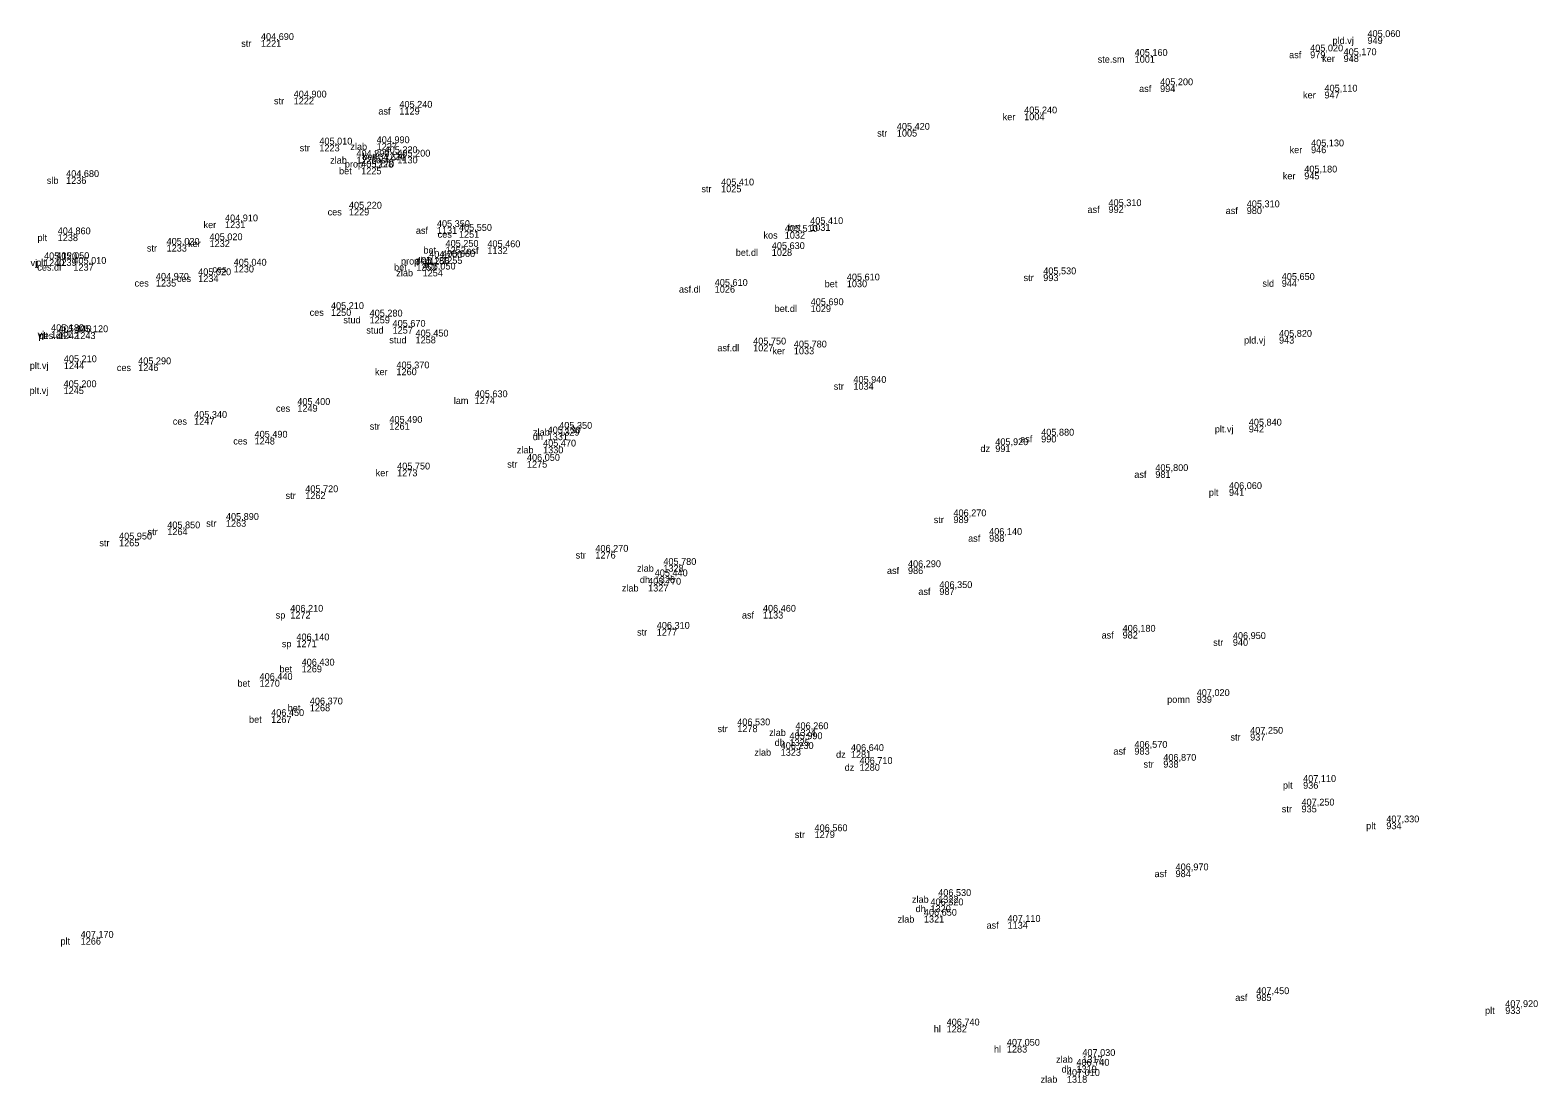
# Model space of a CAD drawing. Extents: x -747136 to -746138, y -1093274 to -1091717.
# Drawn here: x -747041.3 to -746975, y -1092218.2 to -1092171.8 of the extents above; entities that cross this region are included whole.
import ezdxf

# ---------------------------------------------------------------- set-up
doc = ezdxf.new("R2010")
doc.units = 0
for name, color, linetype in [('1029', 7, 'Continuous'), ('404', 7, 'Continuous'), ('424', 7, 'Continuous')]:
    doc.layers.add(name, color=color, linetype=linetype)

msp = doc.modelspace()

# ---------------------------------------------------------------- linework, layer by layer
at = {"layer": '404'}
for p, q in [((-747031.19, -1092172.27), (-747031.19, -1092172.27)), ((-746982.52, -1092172.14), (-746982.52, -1092172.14)), ((-746992.76, -1092172.97), (-746992.76, -1092172.97)), ((-746985.04, -1092172.77), (-746985.04, -1092172.77)), ((-746983.57, -1092172.94), (-746983.57, -1092172.94)), ((-746991.64, -1092174.26), (-746991.64, -1092174.26)), ((-747029.75, -1092174.8), (-747029.75, -1092174.8)), ((-746984.41, -1092174.54), (-746984.41, -1092174.54)), ((-747025.1, -1092175.25), (-747025.1, -1092175.25)), ((-746997.62, -1092175.5), (-746997.62, -1092175.5)), ((-747003.22, -1092176.22), (-747003.22, -1092176.22)), ((-747028.62, -1092176.87), (-747028.62, -1092176.87)), ((-747026.1, -1092176.81), (-747026.1, -1092176.81)), ((-746985, -1092176.95), (-746985, -1092176.95)), ((-747026.99, -1092177.41), (-747026.99, -1092177.41)), ((-747026.26, -1092177.58), (-747026.26, -1092177.58)), ((-747025.75, -1092177.25), (-747025.75, -1092177.25)), ((-747025.19, -1092177.4), (-747025.19, -1092177.4)), ((-747039.76, -1092178.3), (-747039.76, -1092178.3)), ((-747026.78, -1092177.88), (-747026.78, -1092177.88)), ((-746985.3, -1092178.1), (-746985.3, -1092178.1)), ((-747010.95, -1092178.67), (-747010.95, -1092178.67)), ((-747027.32, -1092179.69), (-747027.32, -1092179.69)), ((-746993.91, -1092179.58), (-746993.91, -1092179.58)), ((-746987.83, -1092179.63), (-746987.83, -1092179.63)), ((-747032.77, -1092180.25), (-747032.77, -1092180.25)), ((-747007.03, -1092180.37), (-747007.03, -1092180.37)), ((-747040.13, -1092180.82), (-747040.13, -1092180.82)), ((-747033.45, -1092181.08), (-747033.45, -1092181.08)), ((-747023.45, -1092180.5), (-747023.45, -1092180.5)), ((-747022.48, -1092180.67), (-747022.48, -1092180.67)), ((-747008.15, -1092180.71), (-747008.15, -1092180.71)), ((-747035.34, -1092181.28), (-747035.34, -1092181.28)), ((-747023.07, -1092181.37), (-747023.07, -1092181.37)), ((-747021.23, -1092181.39), (-747021.23, -1092181.39)), ((-747008.72, -1092181.47), (-747008.72, -1092181.47)), ((-747040.73, -1092181.92), (-747040.73, -1092181.92)), ((-747040.19, -1092181.91), (-747040.19, -1092181.91)), ((-747039.44, -1092182.12), (-747039.44, -1092182.12)), ((-747032.39, -1092182.2), (-747032.39, -1092182.2)), ((-747024.36, -1092182.12), (-747024.36, -1092182.12)), ((-747024.08, -1092182.37), (-747024.08, -1092182.37)), ((-747023.79, -1092181.85), (-747023.79, -1092181.85)), ((-747023.22, -1092181.82), (-747023.22, -1092181.82)), ((-747035.81, -1092182.82), (-747035.81, -1092182.82)), ((-747033.95, -1092182.62), (-747033.95, -1092182.62)), ((-747011.23, -1092183.09), (-747011.23, -1092183.09)), ((-747005.42, -1092182.85), (-747005.42, -1092182.85)), ((-746996.78, -1092182.58), (-746996.78, -1092182.58)), ((-746986.29, -1092182.83), (-746986.29, -1092182.83)), ((-747028.11, -1092184.11), (-747028.11, -1092184.11)), ((-747026.41, -1092184.44), (-747026.41, -1092184.44)), ((-747007.01, -1092183.94), (-747007.01, -1092183.94)), ((-747040.42, -1092185.08), (-747040.42, -1092185.08)), ((-747025.4, -1092184.89), (-747025.4, -1092184.89)), ((-747040.09, -1092185.13), (-747040.09, -1092185.13)), ((-747039.36, -1092185.13), (-747039.36, -1092185.13)), ((-747024.39, -1092185.32), (-747024.39, -1092185.32)), ((-747009.54, -1092185.67), (-747009.54, -1092185.67)), ((-746986.41, -1092185.33), (-746986.41, -1092185.33)), ((-747007.75, -1092185.8), (-747007.75, -1092185.8)), ((-747039.86, -1092186.45), (-747039.86, -1092186.45)), ((-747036.59, -1092186.54), (-747036.59, -1092186.54)), ((-747025.23, -1092186.72), (-747025.23, -1092186.72)), ((-747039.87, -1092187.55), (-747039.87, -1092187.55)), ((-747005.13, -1092187.36), (-747005.13, -1092187.36)), ((-747029.59, -1092188.33), (-747029.59, -1092188.33)), ((-747021.79, -1092187.99), (-747021.79, -1092187.99)), ((-747034.13, -1092188.9), (-747034.13, -1092188.9)), ((-747025.54, -1092189.12), (-747025.54, -1092189.12)), ((-747018.58, -1092189.58), (-747018.58, -1092189.58)), ((-747018.07, -1092189.38), (-747018.07, -1092189.38)), ((-746996.87, -1092189.68), (-746996.87, -1092189.68)), ((-746987.74, -1092189.24), (-746987.74, -1092189.24)), ((-747031.47, -1092189.77), (-747031.47, -1092189.77)), ((-747018.78, -1092190.16), (-747018.78, -1092190.16)), ((-746998.89, -1092190.1), (-746998.89, -1092190.1)), ((-747019.49, -1092190.79), (-747019.49, -1092190.79)), ((-747025.2, -1092191.17), (-747025.2, -1092191.17)), ((-746991.85, -1092191.24), (-746991.85, -1092191.24)), ((-747029.24, -1092192.17), (-747029.24, -1092192.17)), ((-746988.61, -1092192.03), (-746988.61, -1092192.03)), ((-747032.73, -1092193.39), (-747032.73, -1092193.39)), ((-747000.73, -1092193.23), (-747000.73, -1092193.23)), ((-747037.43, -1092194.25), (-747037.43, -1092194.25)), ((-747035.31, -1092193.76), (-747035.31, -1092193.76)), ((-746999.16, -1092194.05), (-746999.16, -1092194.05)), ((-747016.48, -1092194.79), (-747016.48, -1092194.79)), ((-747013.49, -1092195.37), (-747013.49, -1092195.37)), ((-747002.73, -1092195.47), (-747002.73, -1092195.47)), ((-747014.16, -1092196.24), (-747014.16, -1092196.24)), ((-747013.87, -1092195.87), (-747013.87, -1092195.87)), ((-747001.35, -1092196.39), (-747001.35, -1092196.39)), ((-747029.9, -1092197.43), (-747029.9, -1092197.43)), ((-747009.11, -1092197.43), (-747009.11, -1092197.43)), ((-747013.78, -1092198.18), (-747013.78, -1092198.18)), ((-746993.29, -1092198.31), (-746993.29, -1092198.31)), ((-747029.63, -1092198.69), (-747029.63, -1092198.69)), ((-746988.44, -1092198.63), (-746988.44, -1092198.63)), ((-747029.4, -1092199.8), (-747029.4, -1092199.8)), ((-747031.25, -1092200.43), (-747031.25, -1092200.43)), ((-747029.04, -1092201.51), (-747029.04, -1092201.51)), ((-746990.03, -1092201.14), (-746990.03, -1092201.14)), ((-747030.74, -1092202.02), (-747030.74, -1092202.02)), ((-747010.24, -1092202.43), (-747010.24, -1092202.43)), ((-747007.68, -1092202.6), (-747007.68, -1092202.6)), ((-746987.68, -1092202.8), (-746987.68, -1092202.8)), ((-747008.33, -1092203.47), (-747008.33, -1092203.47)), ((-747007.94, -1092203.04), (-747007.94, -1092203.04)), ((-747005.24, -1092203.56), (-747005.24, -1092203.56)), ((-746992.77, -1092203.42), (-746992.77, -1092203.42)), ((-747004.86, -1092204.13), (-747004.86, -1092204.13)), ((-746991.5, -1092203.99), (-746991.5, -1092203.99)), ((-746985.35, -1092204.92), (-746985.35, -1092204.92)), ((-746985.42, -1092205.96), (-746985.42, -1092205.96)), ((-746981.69, -1092206.7), (-746981.69, -1092206.7)), ((-747006.84, -1092207.09), (-747006.84, -1092207.09)), ((-746990.96, -1092208.81), (-746990.96, -1092208.81)), ((-747001.4, -1092209.94), (-747001.4, -1092209.94)), ((-747002.03, -1092210.81), (-747002.03, -1092210.81)), ((-747001.74, -1092210.35), (-747001.74, -1092210.35)), ((-746998.35, -1092211.08), (-746998.35, -1092211.08)), ((-747039.12, -1092211.78), (-747039.12, -1092211.78)), ((-746987.41, -1092214.26), (-746987.41, -1092214.26)), ((-746976.46, -1092214.83), (-746976.46, -1092214.83)), ((-747001.03, -1092215.64), (-747001.03, -1092215.64)), ((-746998.38, -1092216.53), (-746998.38, -1092216.53)), ((-746995.32, -1092217.41), (-746995.32, -1092217.41)), ((-746995.06, -1092216.98), (-746995.06, -1092216.98)), ((-746995.74, -1092217.86), (-746995.74, -1092217.86))]:
    msp.add_line(p, q, dxfattribs=at)

# ---------------------------------------------------------------- texts
at = {"layer": '1029'}
for s, p in [('405,060', (-746982.52, -1092172.14)), ('404,690', (-747031.19, -1092172.27)), ('405,020', (-746985.04, -1092172.77)), ('405,160', (-746992.76, -1092172.97)), ('405,170', (-746983.57, -1092172.94)), ('404,900', (-747029.75, -1092174.8)), ('405,200', (-746991.64, -1092174.26)), ('405,110', (-746984.41, -1092174.54)), ('405,240', (-747025.1, -1092175.25)), ('405,240', (-746997.62, -1092175.5)), ('405,420', (-747003.22, -1092176.22)), ('405,010', (-747028.62, -1092176.87)), ('404,890', (-747026.99, -1092177.41)), ('404,990', (-747026.1, -1092176.81)), ('405,220', (-747025.75, -1092177.25)), ('405,200', (-747025.19, -1092177.4)), ('405,130', (-746985, -1092176.95)), ('405,170', (-747026.78, -1092177.88)), ('404,670', (-747026.26, -1092177.58)), ('405,180', (-746985.3, -1092178.1)), ('404,680', (-747039.76, -1092178.3)), ('405,410', (-747010.95, -1092178.67)), ('405,220', (-747027.32, -1092179.69)), ('405,310', (-746993.91, -1092179.58)), ('405,310', (-746987.83, -1092179.63)), ('404,910', (-747032.77, -1092180.25)), ('405,350', (-747023.45, -1092180.5)), ('405,550', (-747022.48, -1092180.67)), ('405,510', (-747008.15, -1092180.71)), ('405,410', (-747007.03, -1092180.37)), ('404,860', (-747040.13, -1092180.82)), ('405,030', (-747035.34, -1092181.28)), ('405,020', (-747033.45, -1092181.08)), ('405,250', (-747023.07, -1092181.37)), ('405,460', (-747021.23, -1092181.39)), ('405,120', (-747040.73, -1092181.92)), ('405,050', (-747040.19, -1092181.91)), ('404,700', (-747023.79, -1092181.85)), ('405,060', (-747023.22, -1092181.82)), ('405,630', (-747008.72, -1092181.47)), ('405,010', (-747039.44, -1092182.12)), ('405,020', (-747033.95, -1092182.62)), ('405,040', (-747032.39, -1092182.2)), ('405,180', (-747024.36, -1092182.12)), ('405,050', (-747024.08, -1092182.37)), ('405,530', (-746996.78, -1092182.58)), ('404,970', (-747035.81, -1092182.82)), ('405,610', (-747011.23, -1092183.09)), ('405,610', (-747005.42, -1092182.85)), ('405,650', (-746986.29, -1092182.83)), ('405,690', (-747007.01, -1092183.94)), ('405,210', (-747028.11, -1092184.11)), ('405,280', (-747026.41, -1092184.44)), ('405,180', (-747040.42, -1092185.08)), ('405,140', (-747040.09, -1092185.13)), ('405,120', (-747039.36, -1092185.13)), ('405,670', (-747025.4, -1092184.89)), ('405,450', (-747024.39, -1092185.32)), ('405,820', (-746986.41, -1092185.33)), ('405,750', (-747009.54, -1092185.67)), ('405,780', (-747007.75, -1092185.8)), ('405,210', (-747039.86, -1092186.45)), ('405,290', (-747036.59, -1092186.54)), ('405,370', (-747025.23, -1092186.72)), ('405,940', (-747005.13, -1092187.36)), ('405,200', (-747039.87, -1092187.55)), ('405,630', (-747021.79, -1092187.99)), ('405,400', (-747029.59, -1092188.33)), ('405,340', (-747034.13, -1092188.9)), ('405,490', (-747025.54, -1092189.12)), ('405,350', (-747018.07, -1092189.38)), ('405,840', (-746987.74, -1092189.24)), ('405,490', (-747031.47, -1092189.77)), ('405,130', (-747018.58, -1092189.58)), ('405,880', (-746996.87, -1092189.68)), ('405,470', (-747018.78, -1092190.16)), ('405,920', (-746998.89, -1092190.1)), ('405,750', (-747025.2, -1092191.17)), ('406,050', (-747019.49, -1092190.79)), ('405,800', (-746991.85, -1092191.24)), ('406,060', (-746988.61, -1092192.03)), ('405,720', (-747029.24, -1092192.17)), ('406,270', (-747000.73, -1092193.23)), ('405,850', (-747035.31, -1092193.76)), ('405,890', (-747032.73, -1092193.39)), ('405,950', (-747037.43, -1092194.25)), ('406,140', (-746999.16, -1092194.05)), ('406,270', (-747016.48, -1092194.79)), ('405,440', (-747013.87, -1092195.87)), ('405,780', (-747013.49, -1092195.37)), ('406,290', (-747002.73, -1092195.47)), ('405,770', (-747014.16, -1092196.24)), ('406,350', (-747001.35, -1092196.39)), ('406,210', (-747029.9, -1092197.43)), ('406,460', (-747009.11, -1092197.43)), ('406,310', (-747013.78, -1092198.18)), ('406,180', (-746993.29, -1092198.31)), ('406,950', (-746988.44, -1092198.63)), ('406,140', (-747029.63, -1092198.69)), ('406,430', (-747029.4, -1092199.8)), ('406,440', (-747031.25, -1092200.43)), ('407,020', (-746990.03, -1092201.14)), ('406,370', (-747029.04, -1092201.51)), ('406,450', (-747030.74, -1092202.02)), ('406,530', (-747010.24, -1092202.43)), ('406,260', (-747007.68, -1092202.6)), ('405,990', (-747007.94, -1092203.04)), ('407,250', (-746987.68, -1092202.8)), ('406,230', (-747008.33, -1092203.47)), ('406,640', (-747005.24, -1092203.56)), ('406,570', (-746992.77, -1092203.42)), ('406,710', (-747004.86, -1092204.13)), ('406,870', (-746991.5, -1092203.99)), ('407,110', (-746985.35, -1092204.92)), ('407,250', (-746985.42, -1092205.96)), ('406,560', (-747006.84, -1092207.09)), ('407,330', (-746981.69, -1092206.7)), ('406,970', (-746990.96, -1092208.81)), ('406,530', (-747001.4, -1092209.94)), ('406,320', (-747001.74, -1092210.35)), ('406,650', (-747002.03, -1092210.81)), ('407,110', (-746998.35, -1092211.08)), ('407,170', (-747039.12, -1092211.78)), ('407,450', (-746987.41, -1092214.26)), ('407,920', (-746976.46, -1092214.83)), ('406,740', (-747001.03, -1092215.64)), ('407,050', (-746998.38, -1092216.53)), ('407,030', (-746995.06, -1092216.98)), ('407,010', (-746995.74, -1092217.86)), ('406,740', (-746995.32, -1092217.41))]:
    msp.add_text(s, height=0.3, dxfattribs=at).set_placement(p)
at = {"layer": '424'}
for s, p in [(' str', (-747032.168, -1092172.57)), ('1221', (-747031.19, -1092172.57)), (' pld.vj', (-746984.169, -1092172.44)), ('949', (-746982.52, -1092172.44)), (' ste.sm', (-746994.498, -1092173.27)), ('1001', (-746992.76, -1092173.27)), (' asf', (-746986.077, -1092173.07)), ('979', (-746985.04, -1092173.07)), (' ker', (-746984.626, -1092173.24)), ('948', (-746983.57, -1092173.24)), (' asf', (-746992.677, -1092174.56)), ('994', (-746991.64, -1092174.56)), (' str', (-747030.728, -1092175.1)), ('1222', (-747029.75, -1092175.1)), (' ker', (-746985.466, -1092174.84)), ('947', (-746984.41, -1092174.84)), (' asf', (-747026.137, -1092175.55)), ('1129', (-747025.1, -1092175.55)), (' ker', (-746998.676, -1092175.8)), ('1004', (-746997.62, -1092175.8)), (' str', (-747004.198, -1092176.52)), ('1005', (-747003.22, -1092176.52)), (' str', (-747029.598, -1092177.17)), ('1223', (-747028.62, -1092177.17)), (' zlab', (-747027.368, -1092177.11)), ('1227', (-747026.1, -1092177.11)), (' ker', (-746986.056, -1092177.25)), ('946', (-746985, -1092177.25)), (' zlab', (-747028.258, -1092177.71)), (' prop', (-747027.611, -1092177.88)), ('1226', (-747026.99, -1092177.71)), (' bet', (-747026.836, -1092177.55)), ('1228', (-747026.26, -1092177.88)), (' asf', (-747026.227, -1092177.7)), ('1224', (-747025.75, -1092177.55)), ('1130', (-747025.19, -1092177.7)), (' slb', (-747040.721, -1092178.6)), ('1236', (-747039.76, -1092178.6)), (' bet', (-747027.866, -1092178.18)), ('1225', (-747026.78, -1092178.18)), (' ker', (-746986.356, -1092178.4)), ('945', (-746985.3, -1092178.4)), (' str', (-747011.928, -1092178.97)), ('1025', (-747010.95, -1092178.97)), (' ces', (-747028.369, -1092179.99)), ('1229', (-747027.32, -1092179.99)), (' asf', (-746994.947, -1092179.88)), ('992', (-746993.91, -1092179.88)), (' asf', (-746988.867, -1092179.93)), ('980', (-746987.83, -1092179.93)), (' ker', (-747033.826, -1092180.55)), ('1231', (-747032.77, -1092180.55)), (' bet', (-747008.116, -1092180.67)), ('1031', (-747007.03, -1092180.67)), (' plt', (-747041.129, -1092181.12)), ('1238', (-747040.13, -1092181.12)), (' ker', (-747034.506, -1092181.38)), ('1232', (-747033.45, -1092181.38)), (' asf', (-747024.487, -1092180.8)), ('1131', (-747023.45, -1092180.8)), (' ces', (-747023.529, -1092180.97)), ('1251', (-747022.48, -1092180.97)), (' kos', (-747009.199, -1092181.01)), ('1032', (-747008.15, -1092181.01)), (' str', (-747036.318, -1092181.58)), ('1233', (-747035.34, -1092181.58)), (' bet', (-747024.156, -1092181.67)), ('1252', (-747023.07, -1092181.67)), (' asf', (-747022.267, -1092181.69)), ('1132', (-747021.23, -1092181.69)), (' bet.dl', (-747010.416, -1092181.77)), ('1028', (-747008.72, -1092181.77)), (' vj', (-747041.434, -1092182.22)), (' plt', (-747041.189, -1092182.21)), (' ces.dl', (-747041.138, -1092182.42)), ('1240', (-747040.73, -1092182.22)), ('1239', (-747040.19, -1092182.21)), ('1237', (-747039.44, -1092182.42)), (' ces', (-747033.439, -1092182.5)), ('1230', (-747032.39, -1092182.5)), (' bet', (-747025.446, -1092182.42)), (' zlab', (-747025.348, -1092182.67)), (' prop', (-747025.141, -1092182.15)), (' zlab', (-747024.488, -1092182.12)), ('1253', (-747024.36, -1092182.42)), ('1254', (-747024.08, -1092182.67)), ('1256', (-747023.79, -1092182.15)), ('1255', (-747023.22, -1092182.12)), (' ces', (-747036.859, -1092183.12)), ('1235', (-747035.81, -1092183.12)), (' ces', (-747034.999, -1092182.92)), ('1234', (-747033.95, -1092182.92)), (' asf.dl', (-747012.916, -1092183.39)), ('1026', (-747011.23, -1092183.39)), (' bet', (-747006.506, -1092183.15)), ('1030', (-747005.42, -1092183.15)), (' str', (-746997.758, -1092182.88)), ('993', (-746996.78, -1092182.88)), (' sld', (-746987.251, -1092183.13)), ('944', (-746986.29, -1092183.13)), (' ces', (-747029.159, -1092184.41)), ('1250', (-747028.11, -1092184.41)), (' stud', (-747027.676, -1092184.74)), ('1259', (-747026.41, -1092184.74)), (' bet.dl', (-747008.706, -1092184.24)), ('1029', (-747007.01, -1092184.24)), (' vj', (-747041.124, -1092185.38)), ('1241', (-747040.42, -1092185.38)), (' stud', (-747026.666, -1092185.19)), ('1257', (-747025.4, -1092185.19)), (' plt', (-747041.089, -1092185.43)), (' ces.dl', (-747041.058, -1092185.43)), ('1242', (-747040.09, -1092185.43)), ('1243', (-747039.36, -1092185.43)), (' stud', (-747025.656, -1092185.62)), ('1258', (-747024.39, -1092185.62)), (' asf.dl', (-747011.226, -1092185.97)), ('1027', (-747009.54, -1092185.97)), (' pld.vj', (-746988.059, -1092185.63)), ('943', (-746986.41, -1092185.63)), (' ker', (-747008.806, -1092186.1)), ('1033', (-747007.75, -1092186.1)), (' plt.vj', (-747041.468, -1092186.75)), ('1244', (-747039.86, -1092186.75)), (' ces', (-747037.639, -1092186.84)), ('1246', (-747036.59, -1092186.84)), (' ker', (-747026.286, -1092187.02)), ('1260', (-747025.23, -1092187.02)), (' plt.vj', (-747041.478, -1092187.85)), ('1245', (-747039.87, -1092187.85)), (' str', (-747006.108, -1092187.66)), ('1034', (-747005.13, -1092187.66)), (' ces', (-747030.639, -1092188.63)), ('1249', (-747029.59, -1092188.63)), (' lam', (-747022.82, -1092188.29)), ('1274', (-747021.79, -1092188.29)), (' ces', (-747035.179, -1092189.2)), ('1247', (-747034.13, -1092189.2)), (' str', (-747026.518, -1092189.42)), ('1261', (-747025.54, -1092189.42)), (' dh', (-747019.345, -1092189.88)), (' zlab', (-747019.338, -1092189.68)), ('1331', (-747018.58, -1092189.88)), ('1329', (-747018.07, -1092189.68)), (' asf', (-746997.907, -1092189.98)), ('990', (-746996.87, -1092189.98)), (' plt.vj', (-746989.348, -1092189.54)), ('942', (-746987.74, -1092189.54)), (' ces', (-747032.519, -1092190.07)), ('1248', (-747031.47, -1092190.07)), (' zlab', (-747020.048, -1092190.46)), ('1330', (-747018.78, -1092190.46)), (' dz', (-746999.655, -1092190.4)), ('991', (-746998.89, -1092190.4)), (' str', (-747020.468, -1092191.09)), ('1275', (-747019.49, -1092191.09)), (' ker', (-747026.256, -1092191.47)), ('1273', (-747025.2, -1092191.47)), (' asf', (-746992.887, -1092191.54)), ('981', (-746991.85, -1092191.54)), (' str', (-747030.218, -1092192.47)), ('1262', (-747029.24, -1092192.47)), (' plt', (-746989.609, -1092192.33)), ('941', (-746988.61, -1092192.33)), (' str', (-747033.708, -1092193.69)), ('1263', (-747032.73, -1092193.69)), (' str', (-747001.708, -1092193.53)), ('989', (-747000.73, -1092193.53)), (' str', (-747038.408, -1092194.55)), ('1265', (-747037.43, -1092194.55)), (' str', (-747036.288, -1092194.06)), ('1264', (-747035.31, -1092194.06)), (' asf', (-747000.197, -1092194.35)), ('988', (-746999.16, -1092194.35)), (' str', (-747017.458, -1092195.09)), ('1276', (-747016.48, -1092195.09)), (' zlab', (-747014.758, -1092195.67)), ('1328', (-747013.49, -1092195.67)), (' asf', (-747003.767, -1092195.77)), ('986', (-747002.73, -1092195.77)), (' zlab', (-747015.428, -1092196.54)), (' dh', (-747014.635, -1092196.17)), ('1327', (-747014.16, -1092196.54)), ('1326', (-747013.87, -1092196.17)), (' asf', (-747002.387, -1092196.69)), ('987', (-747001.35, -1092196.69)), (' sp', (-747030.653, -1092197.73)), ('1272', (-747029.9, -1092197.73)), (' asf', (-747010.147, -1092197.73)), ('1133', (-747009.11, -1092197.73)), (' str', (-747014.758, -1092198.48)), ('1277', (-747013.78, -1092198.48)), (' asf', (-746994.327, -1092198.61)), ('982', (-746993.29, -1092198.61)), (' sp', (-747030.383, -1092198.99)), ('1271', (-747029.63, -1092198.99)), (' str', (-746989.418, -1092198.93)), ('940', (-746988.44, -1092198.93)), (' bet', (-747030.486, -1092200.1)), ('1269', (-747029.4, -1092200.1)), (' bet', (-747032.336, -1092200.73)), ('1270', (-747031.25, -1092200.73)), (' bet', (-747030.126, -1092201.81)), ('1268', (-747029.04, -1092201.81)), (' pomn', (-746991.442, -1092201.44)), ('939', (-746990.03, -1092201.44)), (' bet', (-747031.826, -1092202.32)), ('1267', (-747030.74, -1092202.32)), (' str', (-747011.218, -1092202.73)), ('1278', (-747010.24, -1092202.73)), (' zlab', (-747008.948, -1092202.9)), ('1324', (-747007.68, -1092202.9)), (' str', (-746988.658, -1092203.1)), ('937', (-746987.68, -1092203.1)), (' zlab', (-747009.598, -1092203.77)), (' dh', (-747008.705, -1092203.34)), ('1323', (-747008.33, -1092203.77)), ('1325', (-747007.94, -1092203.34)), (' dz', (-747006.005, -1092203.86)), ('1281', (-747005.24, -1092203.86)), (' asf', (-746993.807, -1092203.72)), ('983', (-746992.77, -1092203.72)), (' dz', (-747005.625, -1092204.43)), ('1280', (-747004.86, -1092204.43)), (' str', (-746992.478, -1092204.29)), ('938', (-746991.5, -1092204.29)), (' plt', (-746986.349, -1092205.22)), ('936', (-746985.35, -1092205.22)), (' str', (-746986.398, -1092206.26)), ('935', (-746985.42, -1092206.26)), (' plt', (-746982.689, -1092207)), ('934', (-746981.69, -1092207)), (' str', (-747007.818, -1092207.39)), ('1279', (-747006.84, -1092207.39)), (' asf', (-746991.997, -1092209.11)), ('984', (-746990.96, -1092209.11)), (' zlab', (-747002.668, -1092210.24)), ('1322', (-747001.4, -1092210.24)), (' zlab', (-747003.298, -1092211.11)), (' dh', (-747002.505, -1092210.65)), ('1321', (-747002.03, -1092211.11)), ('1320', (-747001.74, -1092210.65)), (' asf', (-746999.387, -1092211.38)), ('1134', (-746998.35, -1092211.38)), (' plt', (-747040.119, -1092212.08)), ('1266', (-747039.12, -1092212.08)), (' asf', (-746988.447, -1092214.56)), ('985', (-746987.41, -1092214.56)), (' plt', (-746977.459, -1092215.13)), ('933', (-746976.46, -1092215.13)), (' hl', (-747001.708, -1092215.94)), ('1282', (-747001.03, -1092215.94)), (' hl', (-746999.058, -1092216.83)), ('1283', (-746998.38, -1092216.83)), (' zlab', (-746996.328, -1092217.28)), (' dh', (-746996.085, -1092217.71)), ('1319', (-746995.32, -1092217.71)), ('1317', (-746995.06, -1092217.28)), (' zlab', (-746997.008, -1092218.16)), ('1318', (-746995.74, -1092218.16))]:
    msp.add_text(s, height=0.3, dxfattribs=at).set_placement(p)

doc.saveas('drawing.dxf')
